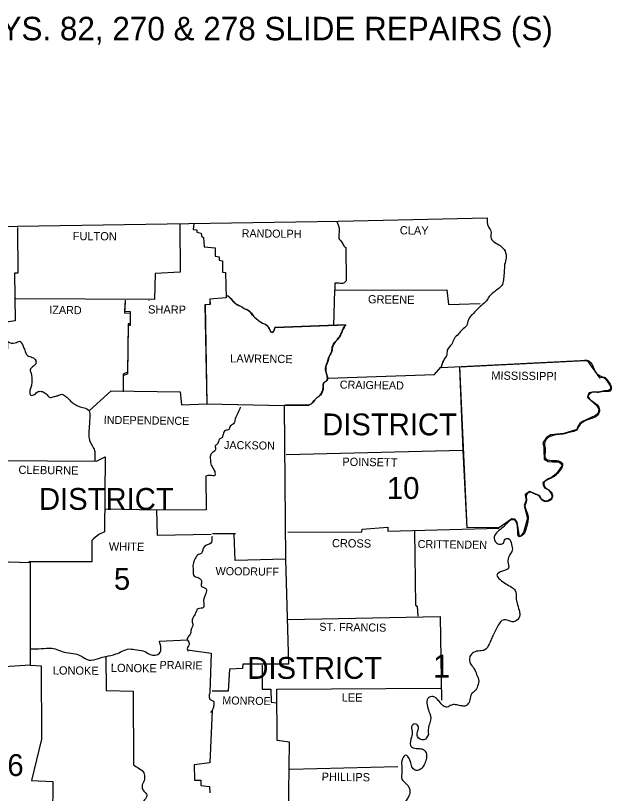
# Model space of a CAD drawing. Extents: x -2512 to 3792, y -435 to 2624.
# Drawn here: x 2999.8 to 3303.9, y 1667 to 2064.2 of the extents above; entities that cross this region are included whole.
import ezdxf

# ---------------------------------------------------------------- set-up
doc = ezdxf.new("R2010")
doc.units = 0
for name, color, linetype in [('1', 7, 'Continuous'), ('2', 7, 'Continuous'), ('3', 7, 'Continuous'), ('R_Border', 7, 'Continuous'), ('S_MISC_BOUNDARY', 7, 'Continuous')]:
    doc.layers.add(name, color=color, linetype=linetype)

msp = doc.modelspace()

# ---------------------------------------------------------------- linework, layer by layer
at = {"layer": '1'}
for p, q in [((3162.68, 1927.56), (3162.68, 1923.94)), ((3108.28, 1921), (3107.18, 1920.97)), ((3130.69, 1902.3), (3131.63, 1903.24)), ((3168.15, 1906.22), (3132.15, 1904.95)), ((3161.99, 1905.92), (3162.17, 1906.1)), ((3216.98, 1884.51), (3218.15, 1888.13)), ((3217.27, 1885.68), (3218.45, 1888.52)), ((3226.44, 1884.86), (3290.81, 1888.03)), ((3290.81, 1888.03), (3291.37, 1888.06)), ((3291.37, 1888.06), (3291.82, 1887.74)), ((3291.82, 1887.74), (3293.06, 1885.95)), ((3230.26, 1802.6), (3226.44, 1884.86)), ((3293.06, 1885.95), (3295.41, 1882.57)), ((3295.41, 1882.57), (3297.76, 1879.19)), ((3297.76, 1879.19), (3298.93, 1879.51)), ((3298.93, 1879.51), (3300.13, 1879.31)), ((3300.13, 1879.31), (3301.22, 1878.2)), ((3301.22, 1878.2), (3302.44, 1876.57)), ((3302.44, 1876.57), (3303.37, 1874.77)), ((3292.13, 1871.02), (3291.68, 1869.22)), ((3292.54, 1871.57), (3292.13, 1871.02)), ((3295.05, 1872.12), (3292.54, 1871.57)), ((3297.13, 1871.88), (3295.05, 1872.12)), ((3300.28, 1872.51), (3297.13, 1871.88)), ((3302.17, 1872.53), (3300.28, 1872.51)), ((3303.38, 1873.39), (3302.17, 1872.53)), ((3303.37, 1874.77), (3303.38, 1873.39)), ((3291.68, 1869.22), (3296.38, 1864.85)), ((3296.38, 1864.85), (3297.46, 1863.25)), ((3297.46, 1863.25), (3297.04, 1861.36)), ((3295.44, 1859.75), (3289.06, 1856.92)), ((3297.04, 1861.36), (3295.44, 1859.75)), ((3287.8, 1855.85), (3286.65, 1854.36)), ((3289.06, 1856.92), (3287.8, 1855.85)), ((3286.16, 1852.93), (3279.52, 1850.83)), ((3286.65, 1854.36), (3286.16, 1852.93)), ((3270.72, 1848.72), (3268.77, 1845.96)), ((3272.94, 1850.13), (3270.72, 1848.72)), ((3279.52, 1850.83), (3272.94, 1850.13)), ((3268.77, 1845.96), (3269.38, 1844.17)), ((3269.38, 1844.17), (3269.38, 1842.29)), ((3269.38, 1842.29), (3269.56, 1837.62)), ((3269.56, 1837.62), (3271.52, 1836.44)), ((3271.52, 1836.44), (3273.82, 1836.37)), ((3273.82, 1836.37), (3276.11, 1836.3)), ((3276.11, 1836.3), (3276.94, 1836.27)), ((3276.94, 1836.27), (3278.02, 1835.47)), ((3278.02, 1835.47), (3278.67, 1834.41)), ((3278.67, 1834.41), (3275.86, 1830.41)), ((3271.5, 1827.68), (3268.87, 1825.55)), ((3273.22, 1828.41), (3271.5, 1827.68)), ((3275.86, 1830.41), (3273.22, 1828.41)), ((3268.87, 1825.55), (3268.96, 1824.55)), ((3268.96, 1824.55), (3269.77, 1823.02)), ((3262.17, 1821.14), (3259.84, 1819.64)), ((3259.84, 1819.64), (3259.96, 1818.51)), ((3264.4, 1820.23), (3262.17, 1821.14)), ((3267.29, 1819.04), (3264.4, 1820.23)), ((3269.77, 1823.02), (3271.69, 1821.96)), ((3271.69, 1821.96), (3273.18, 1820.16)), ((3273.18, 1820.16), (3273.69, 1818.75)), ((3260.3, 1816.83), (3259.31, 1814)), ((3259.96, 1818.51), (3260.3, 1816.83)), ((3268.24, 1817.29), (3267.29, 1819.04)), ((3269.98, 1816.31), (3268.24, 1817.29)), ((3271.38, 1816.37), (3269.98, 1816.31)), ((3273.11, 1817.5), (3271.38, 1816.37)), ((3273.69, 1818.75), (3273.11, 1817.5)), ((3259.31, 1814), (3261.05, 1807.5)), ((3261.05, 1807.5), (3258.99, 1800.18)), ((3253.09, 1807.19), (3246.81, 1802.72)), ((3254.51, 1807.09), (3253.09, 1807.19)), ((3255.79, 1805.51), (3254.51, 1807.09)), ((3257.01, 1798.41), (3255.79, 1805.51)), ((3100.35, 1799.78), (3112, 1799.78)), ((3246.81, 1802.72), (3230.26, 1802.6)), ((3258.99, 1800.18), (3257.56, 1798.6)), ((3257.56, 1798.6), (3257.01, 1798.41))]:
    msp.add_line(p, q, dxfattribs=at)
for points in [[(2703.71, 1956.42), (2861.92, 1956.32), (3000.75, 1956.61), (3164.54, 1959.16), (3240.46, 1960.92)], [(3000.75, 1956.03), (3000.95, 1932.74), (2999.28, 1932.64), (2999.58, 1908.28), (2992.73, 1907.3), (2993.32, 1900.75), (2995.66, 1897.71), (2995.47, 1889.98), (2982.16, 1889.5), (2981.67, 1877.56), (2969.54, 1877.17), (2968.95, 1862.69), (2969.64, 1861.51), (2969.93, 1838.42), (2990.87, 1837.05), (2990.58, 1785.49), (3007.21, 1785), (3007.21, 1732.56), (2994.1, 1731.58), (2993.12, 1720.04), (2971.11, 1719.94)], [(3083.62, 1957.49), (3083.82, 1933.23), (3071.1, 1932.55), (3070.71, 1919.24), (2999.97, 1919.63)], [(3090.74, 1958.01), (3090.37, 1955.05), (3092.33, 1954.76), (3092.23, 1953.58), (3094.48, 1953.09), (3094.68, 1951.53), (3095.75, 1950.84), (3096.05, 1946.15), (3101.63, 1945.56), (3101.63, 1941.35), (3103.68, 1941.06), (3103.68, 1939.39), (3105.44, 1938.9), (3105.34, 1933.23), (3106.91, 1932.94), (3107.3, 1920.12), (3098.98, 1919.34), (3099.08, 1916.6), (3096.54, 1916.5), (3097.42, 1866.01), (3136.85, 1865.13), (3137.53, 1786.66), (3111.8, 1785.98), (3111.31, 1799.19)], [(3168.35, 1945.75), (3168.45, 1928.83)], [(3162.16, 1906), (3162.68, 1923.94), (3162.68, 1923.94), (3219.91, 1924.23), (3220.7, 1916.6), (3236.84, 1917.18)], [(3055.64, 1918.95), (3055.44, 1913.27), (3058.18, 1913.07), (3058.28, 1906.81), (3057.3, 1906.81), (3056.91, 1882.16), (3054.66, 1881.18), (3054.66, 1872.96)], [(3067.87, 1918.75), (3067.97, 1918.85)], [(3107.18, 1920.97), (3107.2, 1920.12), (3098.89, 1919.34), (3098.98, 1916.6), (3096.44, 1916.5), (3097.32, 1866.01), (3136.75, 1865.13)], [(3055.64, 1918.06), (3055.44, 1912.39), (3058.18, 1912.19), (3058.28, 1905.93), (3057.3, 1905.93), (3056.91, 1881.28), (3054.66, 1880.3), (3054.66, 1872.08)], [(3132.25, 1904.95), (3168.55, 1906.23)], [(3168.16, 1906.13), (3168.15, 1906.22)], [(3216.98, 1884.51), (3291.24, 1888.32)], [(3159.25, 1879.12), (3213.55, 1880.89), (3216.78, 1884.6)], [(3226.37, 1884.41), (3228.04, 1842.04), (3229.99, 1802.61)], [(3037.44, 1862.49), (3048.6, 1872.57), (3083.82, 1872.08), (3084.5, 1865.52), (3097.32, 1866.01)], [(3136.75, 1865.13), (3137.63, 1865.33), (3149.57, 1865.33)], [(3149.67, 1865.33), (3137.73, 1865.33), (3136.85, 1865.13)], [(3228.04, 1842.04), (3137.92, 1839.99)], [(2990.87, 1837.05), (3041.16, 1836.76), (3045.46, 1838.81), (3045.17, 1800.56), (3042.24, 1799.29), (3039.59, 1797.04), (3038.71, 1796.16), (3038.62, 1785.2), (3006.62, 1785.2)], [(3096.93, 1829.03), (3097.12, 1811.81), (3071.69, 1811.71), (3045.56, 1812.2)], [(3071.69, 1811.71), (3072.08, 1798.89), (3099.57, 1799.38)], [(3138.71, 1800.36), (3176.47, 1800.56), (3176.57, 1801.93), (3189.68, 1802.91), (3189.68, 1800.85), (3246.63, 1802.42)], [(3203.38, 1800.85), (3203.87, 1763.18), (3204.75, 1762.6), (3205.04, 1757.51)], [(3100.35, 1798.11), (3099.86, 1798.01)], [(3137.53, 1786.66), (3139, 1733.05), (3115.71, 1732.95), (3115.62, 1730.8), (3108.87, 1730.41), (3108.28, 1719.25), (3100.06, 1719.25)], [(3138.71, 1755.85), (3216.39, 1757.41)], [(3216.39, 1757.41), (3217.18, 1714.56)], [(3073.25, 1744.69), (3087.44, 1745.38)], [(3087.44, 1740.29), (3099.67, 1738.72), (3098.98, 1718.76)], [(3045.86, 1737.06), (3046.05, 1719.55), (3059.85, 1719.25), (3059.95, 1681.68)], [(3007.21, 1732.56), (3012.88, 1732.17), (3012.98, 1694.79), (3007.89, 1673.56), (3018.75, 1673.07), (3018.66, 1655.07)], [(3125.69, 1732.46), (3125.6, 1720.33), (3130.1, 1720.33), (3130.29, 1713.58), (3133.13, 1713.28)], [(3138.71, 1633.54), (3146.34, 1634.03), (3146.24, 1653.9), (3139.1, 1654.38), (3139.49, 1693.23), (3133.33, 1694.11), (3133.13, 1720.23), (3216.59, 1720.82)], [(3100.06, 1709.37), (3098.89, 1682.56), (3090.86, 1681.68), (3091.06, 1673.76), (3094.29, 1673.85), (3094.39, 1671.11), (3098.79, 1670.63), (3098.89, 1667.4)], [(3139.69, 1679.43), (3194.87, 1680.8)]]:
    msp.add_lwpolyline(points, dxfattribs=at)
for points in [[(3163.59, 1959.15), (3164.93, 1955.44), (3164.83, 1952.8), (3164.83, 1950.35), (3166.1, 1948.69), (3167.37, 1946.63), (3168.35, 1945.75)], [(3240.46, 1960.92), (3240.95, 1956.61), (3242.32, 1954.36), (3242.52, 1950.25), (3244.18, 1948.49), (3247.02, 1946.73), (3249.56, 1943.89), (3250.15, 1940.57), (3249.36, 1937.14), (3249.17, 1933.33), (3248.78, 1930), (3248.19, 1926.97), (3245.84, 1924.52), (3243.59, 1922.76), (3241.54, 1920.71), (3240.07, 1918.55), (3237.53, 1916.21), (3234.98, 1913.76), (3232.93, 1911.61), (3230.87, 1908.87), (3229.89, 1905.83), (3227.64, 1903.68), (3225.88, 1901.73), (3223.53, 1899.08), (3222.36, 1896.44), (3220.11, 1893.41), (3219.62, 1890.47), (3218.15, 1888.13), (3218.06, 1887.73)], [(3168.45, 1928.83), (3167.18, 1927.56), (3164.73, 1927.56), (3162.68, 1927.56)], [(3132.15, 1904.95), (3130.59, 1902.31), (3129.12, 1904.37), (3128.04, 1906.03), (3124.81, 1907.6), (3122.76, 1909.26), (3120.7, 1911.31), (3119.24, 1913.17), (3116.99, 1914.35), (3114.44, 1915.81), (3112.29, 1916.89), (3110.43, 1918.75), (3108.28, 1921)], [(3108.38, 1921), (3110.53, 1918.75), (3112.39, 1916.89), (3114.54, 1915.81), (3117.08, 1914.35), (3119.33, 1913.17), (3120.8, 1911.31), (3122.86, 1909.26), (3124.91, 1907.6), (3128.14, 1906.03), (3129.22, 1904.37), (3130.68, 1902.31), (3132.25, 1904.95)], [(3149.57, 1865.33), (3151.03, 1866.31), (3152.99, 1868.56), (3154.85, 1870.03), (3156.12, 1871.98), (3156.71, 1873.94), (3157.1, 1876.78), (3158.57, 1877.85), (3158.76, 1880.1), (3158.08, 1882.55), (3158.08, 1884.99), (3158.96, 1887.34), (3159.74, 1890.08), (3161.11, 1892.82), (3161.41, 1894.88), (3163.17, 1897.91), (3165.52, 1901.04), (3166.69, 1903.78), (3168.16, 1906.13)], [(3168.25, 1906.13), (3166.79, 1903.78), (3165.61, 1901.04), (3163.26, 1897.91), (3161.5, 1894.88), (3161.21, 1892.82), (3159.84, 1890.08), (3159.06, 1887.34), (3158.18, 1884.99), (3158.18, 1882.55), (3158.86, 1880.1), (3158.67, 1877.85), (3157.2, 1876.78), (3156.81, 1873.94), (3156.22, 1871.98), (3154.95, 1870.03), (3153.09, 1868.56), (3151.13, 1866.31), (3149.67, 1865.33)], [(2995.66, 1897.71), (2999.58, 1897.03), (3001.93, 1897.91), (3003.59, 1895.37), (3004.47, 1893.41), (3005.94, 1890.57), (3008.29, 1889.69), (3010.05, 1888.13), (3010.05, 1886.46), (3008.48, 1884.9), (3007.31, 1883.33), (3007.7, 1881.47), (3008.09, 1878.93), (3008.09, 1876.48), (3007.5, 1874.23), (3007.01, 1872.18), (3007.5, 1870.42), (3009.36, 1870.71), (3011.32, 1872.18), (3013.37, 1872.18), (3015.33, 1871.1), (3017.38, 1869.24), (3019.44, 1869.63), (3021.1, 1870.12), (3023.45, 1870.81), (3025.11, 1869.93), (3026.58, 1868.75), (3028.34, 1866.89), (3030.01, 1865.72), (3032.16, 1864.64), (3034.8, 1863.96), (3037.25, 1862.3), (3037.64, 1859.46), (3037.54, 1857.01), (3037.34, 1853.98), (3037.15, 1850.65), (3037.44, 1847.42), (3038.52, 1845.27), (3039.89, 1842.73), (3040.28, 1840.38), (3040.18, 1836.66)], [(3290.16, 1888.22), (3291.24, 1888.32), (3294.57, 1884.8), (3296.03, 1881.86), (3298.19, 1880.2), (3300.63, 1879.32), (3302.49, 1877.07), (3303.76, 1874.62), (3303.08, 1872.47), (3300.34, 1872.28), (3297.31, 1871.79), (3294.37, 1871.88), (3292.02, 1869.93), (3294.18, 1867.29), (3297.01, 1864.84), (3297.8, 1862.2), (3296.23, 1859.65), (3293.1, 1858.28), (3290.07, 1857.11), (3287.33, 1854.76), (3286.05, 1852.51), (3283.02, 1851.53), (3279.89, 1850.65), (3277.15, 1850.36), (3274.02, 1849.77), (3270.99, 1848.3), (3269.72, 1845.76), (3270.11, 1842.14), (3270.01, 1838.32), (3273.24, 1837.05), (3276.08, 1836.95), (3278.81, 1835.49), (3278.52, 1833.33), (3276.47, 1830.6), (3274.02, 1828.44), (3271.57, 1827.37), (3269.32, 1825.31), (3270.11, 1823.26), (3272.16, 1821.89), (3273.63, 1819.64), (3273.43, 1817.58), (3271.09, 1816.11), (3268.54, 1816.7), (3266.68, 1819.15), (3264.53, 1819.93), (3262.67, 1820.81), (3260.52, 1819.54), (3260.52, 1816.7), (3259.74, 1813.67), (3260.42, 1811.42), (3261.3, 1808.29), (3261.2, 1805.94), (3260.42, 1802.61), (3258.76, 1799.19), (3256.8, 1798.11), (3256.02, 1801.83), (3255.63, 1804.86), (3254.45, 1806.62), (3252.89, 1806.72), (3250.83, 1805.25), (3248.58, 1803), (3245.74, 1800.56), (3244.08, 1798.11), (3244.96, 1795.08), (3247.11, 1794.3), (3248.78, 1794.88), (3249.66, 1796.84), (3251.32, 1797.13), (3252.89, 1794.1)], [(3114.44, 1864.25), (3113.27, 1861.22), (3111.9, 1858.28), (3111.02, 1855.74), (3109.16, 1854.27), (3108.57, 1852.9), (3106.91, 1852.32), (3105.64, 1850.36), (3105.05, 1848.6), (3103.68, 1847.82), (3103, 1845.66), (3101.72, 1844.49), (3101.82, 1842.53), (3100.35, 1841.16), (3099.18, 1839.6), (3099.18, 1837.44), (3099.67, 1834.61), (3100.65, 1832.94), (3101.53, 1830.79), (3101.43, 1829.42), (3098.98, 1829.42), (3096.93, 1829.03)], [(3099.86, 1798.01), (3099.37, 1794.79), (3097.52, 1793.91), (3095.36, 1791.75), (3094.87, 1789.8), (3093.11, 1789.01), (3091.45, 1786.96), (3090.37, 1784.12), (3090.37, 1781.19), (3091.06, 1777.86), (3093.5, 1776.98), (3094.68, 1775.02), (3094.48, 1772.97), (3096.83, 1771.6), (3097.22, 1770.42), (3096.83, 1769.15), (3095.75, 1765.53), (3095.85, 1763.09), (3095.66, 1762.01), (3093.02, 1761.32), (3091.45, 1758.68), (3090.37, 1756.82), (3089.98, 1754.38), (3090.28, 1752.62), (3089.49, 1751.25), (3089.2, 1749.19), (3088.22, 1747.43), (3087.34, 1745.77), (3088.32, 1743.81), (3088.03, 1742.44), (3087.44, 1740.29), (3087.93, 1739.6)], [(3252.89, 1794.1), (3253.28, 1791.26), (3251.62, 1788.23), (3251.03, 1785.2), (3251.32, 1782.16), (3248.19, 1780.5), (3245.45, 1778.54), (3247.02, 1776.2), (3249.95, 1774.04), (3252.89, 1772.38), (3254.75, 1770.72), (3255.24, 1766.71), (3255.72, 1764.16), (3256.7, 1760.64), (3257.09, 1758.19), (3255.33, 1755.26), (3253.28, 1754.67), (3251.13, 1755.36), (3248.58, 1755.55), (3246.53, 1753.59), (3245.06, 1750.86), (3243.59, 1748.12), (3242.52, 1745.77), (3241.44, 1743.22), (3239.29, 1740.29), (3236.65, 1739.8), (3233.51, 1739.02), (3231.66, 1736.86), (3231.95, 1733.24), (3233.71, 1730.8), (3235.08, 1727.76), (3236.06, 1725.12), (3235.57, 1721.8), (3234.2, 1719.35), (3232.44, 1717.88), (3231.66, 1714.75), (3230.38, 1712.4), (3229.21, 1711.62), (3226.86, 1711.82), (3224.32, 1712.31), (3222.16, 1712.11), (3220.11, 1711.03), (3218.06, 1711.72), (3215.9, 1714.07), (3214.14, 1715.83), (3212.19, 1716.51), (3210.13, 1715.44), (3209.74, 1712.21), (3210.72, 1708.88), (3211.6, 1704.38), (3210.72, 1701.64), (3210.42, 1697.14)], [(3007.4, 1740.78), (3012.88, 1740.97), (3018.26, 1741.17), (3021.69, 1740.19), (3025.6, 1738.92), (3030.2, 1738.33), (3033.43, 1737.06), (3037.25, 1735.1), (3042.14, 1735.98), (3045.95, 1736.96), (3050.94, 1738.23), (3054.17, 1739.6), (3057.89, 1740.78), (3061.61, 1740.29), (3065.82, 1739.51), (3068.46, 1737.94), (3073.25, 1738.63), (3073.25, 1744.69)], [(3098.98, 1718.76), (3098.59, 1716.81), (3099.37, 1714.75), (3100.74, 1714.07), (3100.94, 1712.11), (3100.45, 1710.15), (3100.06, 1709.37), (3099.18, 1708.2)], [(3210.42, 1697.14), (3208.17, 1694.3), (3204.85, 1696.06), (3204.85, 1698.41), (3205.34, 1700.86), (3204.16, 1702.42), (3202.11, 1701.74), (3202.11, 1698.71), (3201.91, 1695.77), (3201.32, 1691.56), (3202.69, 1690.29), (3205.83, 1689.9), (3208.08, 1689.31), (3209.45, 1687.06), (3209.35, 1684.32), (3208.27, 1681.68), (3206.71, 1679.53), (3204.26, 1678.75), (3202.3, 1680.02), (3201.52, 1682.56), (3200.64, 1684.81), (3198.98, 1686.48), (3197.22, 1684.62), (3196.82, 1681.19), (3196.92, 1678.26), (3196.92, 1674.25), (3199.47, 1671.6), (3201.03, 1668.57), (3200.54, 1665.83), (3198.68, 1662.6), (3197.9, 1659.77), (3197.12, 1655.95), (3197.22, 1651.74), (3196.53, 1647.63), (3195.16, 1644.89), (3192.62, 1642.64), (3190.95, 1641.18), (3189.58, 1639.71), (3188.9, 1636.77), (3188.41, 1634.72), (3186.55, 1632.27), (3185.08, 1632.08), (3183.91, 1633.05), (3183.52, 1634.72), (3183.52, 1636.38), (3182.74, 1638.04), (3180.29, 1638.73), (3178.33, 1638.63), (3177.45, 1637.26), (3178.72, 1633.45), (3179.21, 1631), (3178.53, 1627.67), (3178.92, 1627.28), (3175.4, 1625.42), (3172.56, 1625.13), (3170.21, 1624.44), (3167.96, 1622.98), (3166.88, 1620.82), (3165.32, 1619.06), (3163.95, 1617.4), (3162.09, 1616.62), (3160.04, 1617.01), (3157.3, 1617.3), (3155.73, 1615.35), (3156.22, 1612.51), (3158.08, 1610.85), (3160.82, 1610.06), (3163.66, 1610.26), (3166.4, 1610.55), (3168.94, 1609.18), (3168.45, 1606.54), (3166, 1605.27), (3162.38, 1604.88), (3159.45, 1605.17), (3155.93, 1604.39), (3154.17, 1602.14), (3155.14, 1598.71), (3158.96, 1597.34), (3160.72, 1594.11), (3160.82, 1591.08), (3159.55, 1587.07), (3157.79, 1585.21), (3154.36, 1584.43), (3151.72, 1583.94), (3151.33, 1579.44), (3150.15, 1577.19), (3148.1, 1576.5), (3145.16, 1577.97), (3143.4, 1578.66), (3141.25, 1579.63), (3138.51, 1581.3), (3136.46, 1581), (3137.04, 1576.7), (3137.24, 1576.5), (3139.59, 1573.27), (3141.94, 1570.73), (3143.01, 1567.7)], [(3059.95, 1681.68), (3062.39, 1680.02), (3064.93, 1678.06), (3065.62, 1675.42), (3065.42, 1673.56), (3064.64, 1672), (3064.45, 1669.55), (3065.62, 1667.79), (3066.7, 1666.32), (3065.62, 1663.68), (3063.76, 1661.23), (3062.78, 1658.49), (3062.1, 1654.38)]]:
    msp.add_spline(points, degree=3, dxfattribs=at)
at = {"layer": 'S_MISC_BOUNDARY'}
msp.add_line((3108.38, 1921), (3107.27, 1920.97), dxfattribs=at)

# ---------------------------------------------------------------- texts
at = {"layer": '1'}
msp.add_text('1', height=11.74, dxfattribs=at).set_placement((3212.77, 1726.2))
at = {"layer": '2'}
for s, height, rotation, p in [('RANDOLPH', 4.109, 359.2583, (3115.13, 1951.04)), ('CLAY', 4.206, 359.2258, (3195.85, 1952.5)), ('FULTON', 4.206, 359.4996, (3028.93, 1949.57)), ('GREENE', 4.207, 359.2361, (3179.6, 1917.28)), ('IZARD', 4.108, 358.9258, (3016.99, 1912)), ('SHARP', 4.206, 359.3905, (3067.38, 1912.1)), ('LAWRENCE', 4.207, 359.2678, (3109.27, 1887.11)), ('MISSISSIPPI', 4.2062, 359.3097, (3242.52, 1878.34)), ('CRAIGHEAD', 4.109, 359.1159, (3165.22, 1873.74)), ('INDEPENDENCE', 4.1081, 359.2187, (3044.78, 1855.74)), ('JACKSON', 4.108, 359.1352, (3106.13, 1842.92)), ('POINSETT', 4.206, 359.1987, (3166.49, 1834.31)), ('CLEBURNE', 4.206, 359.2535, (3001.24, 1830.2)), ('CROSS', 4.206, 359.3839, (3161.21, 1792.73)), ('CRITTENDEN', 4.109, 359.213, (3204.94, 1792.34)), ('WHITE', 4.207, 359.3139, (3047.32, 1791.07)), ('WOODRUFF', 4.108, 359.2748, (3101.82, 1778.54)), ('ST. FRANCIS', 4.1081, 359.2216, (3154.75, 1750.07)), ('LONOKE', 4.207, 359.4974, (3018.75, 1727.76)), ('LONOKE', 4.207, 359.4974, (3048.4, 1729.04)), ('PRAIRIE', 4.109, 359.2116, (3073.25, 1730.6)), ('MONROE', 4.108, 359.0331, (3105.25, 1712.5)), ('LEE', 4.207, 359.4327, (3166.2, 1713.97)), ('PHILLIPS', 4.206, 359.3179, (3155.93, 1673.46))]:
    msp.add_text(s, height=height, rotation=rotation, dxfattribs=at).set_placement(p)
at = {"layer": '3'}
for s, height, p in [('DISTRICT', 11.154, (3156.22, 1849.87)), ('10', 11.154, (3189.29, 1817.39)), ('DISTRICT', 11.154, (3011.71, 1811.81)), ('5', 11.15, (3049.97, 1771.01)), ('DISTRICT', 11.154, (3118.06, 1725.51)), ('DISTRICT 6', 11.154, (2922.67, 1675.91))]:
    msp.add_text(s, height=height, dxfattribs=at).set_placement(p)
at = {"layer": 'R_Border'}
msp.add_text('HWYS. 82, 270 & 278 SLIDE REPAIRS (S)', height=12, dxfattribs=at).set_placement((2965.35, 2051.58))

doc.saveas('drawing.dxf')
